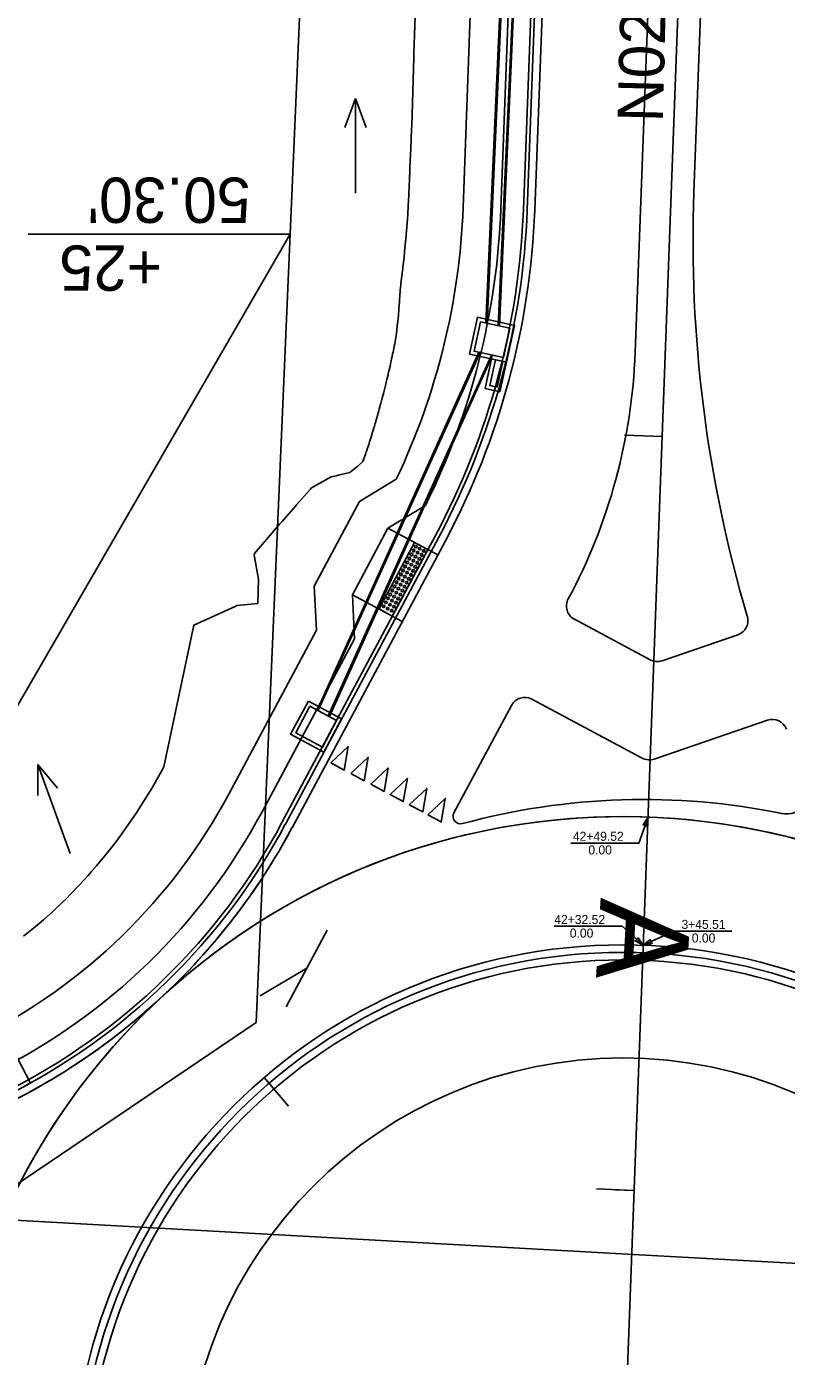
# Model space of a CAD drawing. Extents: x 670017 to 673226, y 705371 to 707498.
# Drawn here: x 671647.7 to 671748.4, y 706559.8 to 706736.1 of the extents above; entities that cross this region are included whole.
import ezdxf

# ---------------------------------------------------------------- set-up
doc = ezdxf.new("R2010")
doc.units = 0
for name, color, linetype in [('EL L 264', 7, 'Continuous'), ('EL L SCBV', 7, 'Continuous'), ('R_Drainage Flow Lines', 7, 'Continuous'), ('R_Drainage Stage 1A', 7, 'Continuous'), ('R_Horz Alg', 7, 'Continuous'), ('R_Horz Alg Station', 7, 'Continuous'), ('R_Horz Bearing', 7, 'Continuous'), ('R_No Plot', 7, 'Continuous'), ('R_No Plot FOC', 7, 'Continuous'), ('R_Proposed Const Limits Stage 1A', 7, 'Continuous'), ('R_Proposed Median', 7, 'Continuous'), ('R_Proposed RAB', 7, 'Continuous'), ('R_Proposed Road Stage 1A', 7, 'Continuous'), ('R_Proposed Sidewalk Stage 1A', 7, 'Continuous'), ('R_ROW', 7, 'Continuous'), ('R_ROW Annot', 7, 'Continuous'), ('R_Striping', 7, 'Continuous'), ('R_Water Annot', 7, 'Continuous'), ('S_EXIST_ROW', 7, 'Continuous')]:
    doc.layers.add(name, color=color, linetype=linetype)

# ---------------------------------------------------------------- blocks, each defined once
blk = doc.blocks.new('FLOW ARROW')
at = {"layer": 'R_Water Annot'}
for p, q in [((-12.57, 0), (0, 0)), ((0, 0), (-3.85, 1.4)), ((0, 0), (-3.85, -1.4))]:
    blk.add_line(p, q, dxfattribs=at)

msp = doc.modelspace()

# ---------------------------------------------------------------- linework, layer by layer
at = {"layer": 'EL L 264'}
for centre, radius, start, end in [((671726.73, 706541.35), 90, 43.8918, 132.897), ((671726.73, 706541.35), 90, 43.8918, 132.897), ((671607.03, 706670.39), 86, 296.5471, 312.7972)]:
    msp.add_arc(centre, radius, start, end, dxfattribs=at)
at = {"layer": 'EL L SCBV'}
for p, q in [((671722.16, 706902.25), (671715.06, 706711.75)), ((671703.22, 706667.92), (671682.89, 706629.86))]:
    msp.add_line(p, q, dxfattribs=at)
for centre, radius, start, end in [((671614.13, 706715.51), 101, 331.8875, 357.8657), ((671607.03, 706670.39), 86, 312.7924, 331.8875), ((671726.73, 706541.35), 90, 132.9015, 220.6505)]:
    msp.add_arc(centre, radius, start, end, dxfattribs=at)
at = {"layer": 'R_Drainage Stage 1A'}
for p, q in [((671708.58, 706696.8), (671717.8, 706902.55)), ((671708.75, 706696.77), (671717.97, 706902.54)), ((671710.23, 706696.44), (671719.47, 706902.44)), ((671710.4, 706696.41), (671719.63, 706902.43)), ((671686.22, 706645.48), (671707.64, 706692.92)), ((671686.37, 706645.4), (671707.81, 706692.88)), ((671687.7, 706644.7), (671709.31, 706692.55)), ((671687.84, 706644.62), (671709.47, 706692.51))]:
    msp.add_line(p, q, dxfattribs=at)
for points in [[(671707.49, 706697.56), (671706.42, 706692.67), (671711.31, 706691.6), (671712.38, 706696.48)], [(671707.87, 706696.96), (671707.02, 706693.05), (671710.92, 706692.2), (671711.78, 706696.1)], [(671711.31, 706691.6), (671710.45, 706687.69), (671708.49, 706688.12), (671709.35, 706692.03)], [(671710.82, 706691.71), (671710.07, 706688.29), (671709.09, 706688.5), (671709.84, 706691.92)], [(671685.06, 706646.67), (671682.71, 706642.26), (671687.12, 706639.9), (671689.47, 706644.31)], [(671685.27, 706645.99), (671683.38, 706642.46), (671686.91, 706640.58), (671688.8, 706644.11)], [(671645.92, 706600.44), (671641.49, 706598.13), (671643.8, 706593.7), (671648.24, 706596.01)]]:
    msp.add_lwpolyline(points, close=True, dxfattribs=at)
at = {"layer": 'R_Horz Alg'}
msp.add_line((671726.73, 706541.35), (671758.33, 707389.39), dxfattribs=at)
msp.add_circle((671726.73, 706541.35), 73, dxfattribs=at)
at = {"layer": 'R_Horz Alg Station'}
for points in [[(671726.96, 706681.92), (671731.96, 706681.73)], [(671729.46, 706681.82), (671731.96, 706681.73)], [(671682.44, 706592.95), (671679.18, 706596.75)], [(671723.24, 706581.98), (671728.23, 706581.8)], [(671725.73, 706581.89), (671728.23, 706581.8)]]:
    msp.add_lwpolyline(points, dxfattribs=at)
at = {"layer": 'R_No Plot'}
for p, q in [((671727.67, 706627.84), (671719.85, 706627.84)), ((671682.13, 706606.15), (671687.55, 706616.31)), ((671725.46, 706616.81), (671717.63, 706616.81)), ((671741.19, 706616.16), (671734.72, 706616.16)), ((671678.68, 706607.57), (671684.86, 706611.28))]:
    msp.add_line(p, q, dxfattribs=at)
for points in [[(671730.08, 706631.29), (671728.87, 706627.84), (671727.67, 706627.84)], [(671729.44, 706614.3), (671726.66, 706616.81), (671725.46, 706616.81)], [(671729.44, 706614.3), (671733.52, 706616.16), (671734.72, 706616.16)]]:
    msp.add_lwpolyline(points, dxfattribs=at)
for points in [[(671730.08, 706631.29), (671729.97, 706630.09), (671729.42, 706630.28)], [(671729.44, 706614.3), (671728.38, 706614.86), (671728.77, 706615.29)], [(671729.44, 706614.3), (671730.38, 706615.05), (671730.62, 706614.52)]]:
    msp.add_lwpolyline(points, close=True, dxfattribs=at)
msp.add_circle((671726.73, 706541.35), 90, dxfattribs=at)
at = {"layer": 'R_No Plot FOC'}
for p, q in [((671714.06, 706711.79), (671721.16, 706902.28)), ((671682.01, 706630.33), (671702.34, 706668.39))]:
    msp.add_line(p, q, dxfattribs=at)
msp.add_circle((671726.73, 706541.35), 72, dxfattribs=at)
for centre, radius, start, end in [((671614.13, 706715.51), 100, 331.8875, 357.8657), ((671607.03, 706670.39), 85, 296.5471, 331.8875)]:
    msp.add_arc(centre, radius, start, end, dxfattribs=at)
at = {"layer": 'R_Proposed Const Limits Stage 1A'}
for points in [[(671692.27, 706678.43), (671692.45, 706678.91), (671692.61, 706679.39), (671692.74, 706679.77), (671692.75, 706679.8), (671692.85, 706680.07), (671693.1, 706680.83), (671693.12, 706680.88), (671693.17, 706681.06), (671693.41, 706681.77), (671693.48, 706681.99), (671693.58, 706682.32), (671693.7, 706682.72), (671693.71, 706682.75), (671693.82, 706683.11), (671693.92, 706683.47), (671693.95, 706683.59), (671694.14, 706684.24), (671694.26, 706684.66), (671694.32, 706684.87), (671694.4, 706685.17), (671694.46, 706685.37), (671694.64, 706686.03), (671694.67, 706686.15), (671694.76, 706686.5), (671694.78, 706686.58), (671694.86, 706686.87), (671695.01, 706687.44), (671695.06, 706687.64), (671695.27, 706688.49), (671695.29, 706688.57), (671695.33, 706688.74), (671695.34, 706688.78), (671695.47, 706689.32), (671695.62, 706689.93), (671695.65, 706690.05), (671695.7, 706690.28), (671695.73, 706690.42), (671695.88, 706691.09), (671695.95, 706691.37), (671696.08, 706692), (671696.14, 706692.25), (671696.16, 706692.36), (671696.22, 706692.62), (671696.23, 706692.7), (671696.28, 706692.94), (671696.38, 706693.42), (671696.44, 706693.73), (671696.51, 706694.05), (671696.56, 706694.32), (671696.61, 706694.59), (671696.73, 706695.42), (671696.74, 706695.49), (671696.78, 706695.79), (671696.8, 706695.98), (671696.84, 706696.32), (671696.89, 706696.81), (671696.9, 706696.9), (671696.91, 706697), (671696.94, 706697.35), (671696.99, 706697.84), (671697.04, 706698.52), (671697.05, 706698.69), (671697.12, 706699.59), (671697.15, 706699.99), (671697.17, 706700.27), (671697.23, 706701.21), (671697.3, 706701.82), (671697.33, 706702.01), (671697.54, 706703.69), (671697.54, 706703.73), (671697.58, 706704.01), (671697.59, 706704.18), (671697.74, 706705.46), (671697.81, 706706.18), (671697.81, 706706.21), (671697.91, 706707.18), (671698.01, 706708.34), (671698.02, 706708.4), (671698.04, 706708.66), (671698.06, 706708.91), (671698.06, 706708.95), (671698.18, 706710.6), (671698.19, 706710.64), (671698.22, 706711.16), (671698.3, 706712.37), (671698.3, 706712.52), (671698.32, 706712.88), (671698.36, 706713.91), (671698.49, 706716.91), (671698.51, 706717.52), (671698.62, 706719.92), (671698.74, 706722.51), (671698.76, 706722.93), (671698.85, 706725.95), (671698.89, 706727.51), (671698.93, 706728.96), (671699.03, 706731.98), (671699.04, 706732.51), (671699.12, 706735), (671699.21, 706737.51)], [(671678.35, 706659.59), (671678.45, 706662.85), (671677.88, 706666.01), (671677.91, 706666.22), (671679.18, 706667.72), (671679.27, 706667.82), (671679.73, 706668.36), (671680.74, 706669.53), (671681.25, 706670.12), (671681.48, 706670.39), (671681.57, 706670.49), (671683.34, 706672.53), (671683.44, 706672.64), (671685.25, 706674.69), (671685.33, 706674.78), (671685.47, 706674.94), (671688.07, 706676.41), (671688.78, 706676.55), (671688.84, 706676.56), (671690.55, 706676.97), (671690.69, 706677.08), (671690.79, 706677.16), (671691.28, 706677.54), (671691.56, 706677.76), (671692.27, 706678.43)], [(671678.35, 706659.59), (671675.63, 706659.35), (671675.35, 706659.22), (671672.61, 706657.96), (671669.86, 706656.72), (671665.91, 706637.95), (671665.56, 706637.3), (671665.37, 706636.96), (671664.34, 706635.17), (671663.31, 706633.48), (671662.54, 706632.28), (671662.27, 706631.87), (671661.23, 706630.34), (671660.18, 706628.88), (671659.48, 706627.94), (671659.12, 706627.48), (671658.27, 706626.39), (671658.05, 706626.12), (671656.97, 706624.81), (671656.32, 706624.06), (671655.86, 706623.53), (671654.74, 706622.3), (671653.56, 706621.12), (671652.99, 706620.5), (671652.4, 706619.92), (671651.18, 706618.78), (671649.93, 706617.66), (671649.38, 706617.19), (671648.63, 706616.57), (671647.29, 706615.49)]]:
    msp.add_lwpolyline(points, dxfattribs=at)
at = {"layer": 'R_Proposed Median'}
for p, q in [((671736.17, 706714.12), (671743.14, 706901.24)), ((671728.37, 706692.88), (671735.41, 706881.66)), ((671720.33, 706657.51), (671730.35, 706652.15)), ((671731.94, 706652.02), (671741.98, 706655.46)), ((671714.68, 706646.92), (671729.3, 706639.11)), ((671704.36, 706631.86), (671711.97, 706646.1)), ((671730.89, 706638.98), (671745.91, 706644.12))]:
    msp.add_line(p, q, dxfattribs=at)
for centre, radius, start, end in [((671911.04, 706707.6), 175, 177.8657, 196.493), ((671653.42, 706695.67), 75, 331.7838, 357.8657), ((671721.27, 706659.27), 2, 151.7838, 241.8875), ((671741.33, 706657.35), 2, 288.9101, 16.493), ((671731.3, 706653.91), 2, 241.8875, 288.9101), ((671713.73, 706645.16), 2, 61.8875, 151.8875), ((671746.56, 706642.23), 2, 21.3677, 108.9101), ((671730.25, 706640.87), 2, 241.8875, 288.9101), ((671748.43, 706634.7), 3, 258.4277, 21.3677), ((671729.47, 706542.12), 91.5, 78.4277, 105.1836), ((671705.24, 706631.39), 1, 151.8875, 285.1836)]:
    msp.add_arc(centre, radius, start, end, dxfattribs=at)
at = {"layer": 'R_Proposed RAB'}
for radius in [71, 58]:
    msp.add_circle((671726.73, 706541.35), radius, dxfattribs=at)
at = {"layer": 'R_Proposed Road Stage 1A'}
for p, q in [((671713.56, 706711.8), (671720.66, 706902.3)), ((671715.06, 706711.75), (671722.16, 706902.25)), ((671681.56, 706630.57), (671701.89, 706668.63)), ((671682.89, 706629.86), (671703.22, 706667.92))]:
    msp.add_line(p, q, dxfattribs=at)
for centre, radius, start, end in [((671614.13, 706715.51), 99.5, 331.8875, 357.8657), ((671614.13, 706715.51), 101, 331.8875, 357.8657), ((671607.03, 706670.39), 84.5, 296.5471, 331.8875), ((671607.03, 706670.39), 86, 296.5471, 331.8875)]:
    msp.add_arc(centre, radius, start, end, dxfattribs=at)
at = {"layer": 'R_Proposed Sidewalk Stage 1A'}
for p, q in [((671705.57, 706712.1), (671712.67, 706902.74)), ((671710.57, 706711.92), (671717.67, 706902.48)), ((671691.84, 706673.14), (671696.71, 706676.11)), ((671691.84, 706673.14), (671685.83, 706661.9)), ((671695.6, 706669.58), (671700.57, 706672.6)), ((671695.6, 706669.58), (671690.89, 706660.76)), ((671702.22, 706666.05), (671695.6, 706669.58)), ((671699.13, 706667.7), (671694.42, 706658.88)), ((671685.83, 706661.9), (671686.12, 706656.07)), ((671697.51, 706657.23), (671690.89, 706660.76)), ((671690.89, 706660.76), (671691.18, 706654.94)), ((671674.51, 706634.34), (671686.12, 706656.07)), ((671678.92, 706631.98), (671691.18, 706654.94))]:
    msp.add_line(p, q, dxfattribs=at)
msp.add_lwpolyline([(671700.89, 706666.75), (671696.18, 706657.93), (671694.42, 706658.88), (671699.13, 706667.7)], close=True, dxfattribs=at)
for centre in [(671699.01, 706666.63), (671699.3, 706667.15), (671699.54, 706666.34), (671699.82, 706666.87), (671700.35, 706666.59), (671697.88, 706664.51), (671698.16, 706665.04), (671698.45, 706665.57), (671698.69, 706664.76), (671698.73, 706666.1), (671698.98, 706665.28), (671699.22, 706664.47), (671699.26, 706665.81), (671699.51, 706665), (671699.79, 706665.53), (671700.07, 706666.06), (671697.03, 706662.92), (671697.32, 706663.45), (671697.56, 706662.64), (671697.6, 706663.98), (671697.85, 706663.17), (671698.13, 706663.7), (671698.37, 706662.88), (671698.41, 706664.23), (671698.66, 706663.41), (671698.94, 706663.94), (671696.19, 706661.33), (671696.47, 706661.86), (671696.71, 706661.05), (671696.75, 706662.39), (671697, 706661.58), (671697.28, 706662.11), (671697.53, 706661.3), (671697.81, 706661.83), (671698.09, 706662.36), (671695.05, 706659.22), (671695.34, 706659.75), (671695.62, 706660.28), (671695.87, 706659.46), (671695.9, 706660.8), (671696.15, 706659.99), (671696.4, 706659.18), (671696.43, 706660.52), (671696.68, 706659.71), (671696.96, 706660.24), (671697.24, 706660.77), (671695.58, 706658.93), (671696.11, 706658.65)]:
    msp.add_circle(centre, 0.165, dxfattribs=at)
for centre, radius, start, end in [((671614.13, 706715.51), 91.5, 334.4926, 357.8657), ((671614.13, 706715.51), 96.5, 333.5967, 357.8657), ((671607.03, 706670.39), 76.5, 296.5471, 331.8875), ((671607.03, 706670.39), 81.5, 296.5471, 331.8875)]:
    msp.add_arc(centre, radius, start, end, dxfattribs=at)
at = {"layer": 'R_ROW'}
msp.add_lwpolyline([(670753.27, 706632.89), (670820.8, 706679.41), (670885.98, 706681), (670933.29, 706628.45), (671562.42, 706595.43), (671640.16, 706635.12), (671682.63, 706708.58)], dxfattribs=at)
at = {"layer": 'R_ROW Annot'}
msp.add_lwpolyline([(671682.63, 706708.58), (671667.92, 706708.57), (671647.92, 706708.57)], dxfattribs=at)
at = {"layer": 'R_Striping'}
for points in [[(671688.04, 706638.46), (671689.81, 706637.52), (671690.34, 706640.64), (671688.04, 706638.46)], [(671690.34, 706640.64), (671688.04, 706638.46)], [(671689.81, 706637.52), (671690.34, 706640.64)], [(671692.99, 706639.23), (671690.69, 706637.05)], [(671690.69, 706637.05), (671692.45, 706636.11), (671692.99, 706639.23), (671690.69, 706637.05)], [(671692.45, 706636.11), (671692.99, 706639.23)], [(671693.34, 706635.64), (671695.1, 706634.69), (671695.63, 706637.81), (671693.34, 706635.64)], [(671695.63, 706637.81), (671693.34, 706635.64)], [(671695.1, 706634.69), (671695.63, 706637.81)], [(671698.18, 706636.46), (671695.88, 706634.28), (671697.64, 706633.34), (671698.18, 706636.46)], [(671698.18, 706636.46), (671695.88, 706634.28)], [(671697.64, 706633.34), (671698.18, 706636.46)], [(671700.74, 706635.09), (671698.44, 706632.91)], [(671698.44, 706632.91), (671700.21, 706631.97), (671700.74, 706635.09), (671698.44, 706632.91)], [(671700.21, 706631.97), (671700.74, 706635.09)], [(671703.2, 706633.77), (671700.91, 706631.6)], [(671700.91, 706631.6), (671702.67, 706630.65), (671703.2, 706633.77), (671700.91, 706631.6)], [(671702.67, 706630.65), (671703.2, 706633.77)]]:
    msp.add_lwpolyline(points, dxfattribs=at)
at = {"layer": 'S_EXIST_ROW'}
for points in [[(671682.63, 706708.58), (671684.53, 706752.74), (671688.75, 706863.46)], [(671639.86, 706578.18), (671678.12, 706604.07), (671682.63, 706708.58)], [(670020.59, 706668.53), (670619.99, 706639.58), (670619.86, 706634.58), (671728.16, 706573.3), (673225.88, 706490.48)]]:
    msp.add_lwpolyline(points, dxfattribs=at)

# ---------------------------------------------------------------- block references
at = {"layer": 'R_Drainage Flow Lines'}
for p, rotation in [((671691.3, 706726.56), 89.99999999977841), ((671649.18, 706638.25), 110.03718328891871)]:
    msp.add_blockref('FLOW ARROW', p, dxfattribs=dict(at, rotation=rotation))

# ---------------------------------------------------------------- texts
at = {"layer": 'R_Horz Alg'}
msp.add_text('A', height=12, rotation=266.6859, dxfattribs=at).set_placement((671723.8, 706620.64))
at = {"layer": 'R_Horz Bearing'}
msp.add_text('N02%%d08\'03"E', height=6, rotation=88.5162, dxfattribs=at).set_placement((671732.03, 706723.36))
at = {"layer": 'R_No Plot'}
for s, p in [('42+49.52', (671720.12, 706628.14)), ('0.00', (671722.17, 706626.34)), ('42+32.52', (671717.65, 706617.11)), ('3+45.51', (671734.51, 706616.46)), ('0.00', (671719.71, 706615.31)), ('0.00', (671735.88, 706614.66))]:
    msp.add_text(s, height=1.2, rotation=360, dxfattribs=at).set_placement(p)
at = {"layer": 'R_ROW Annot'}
for s, p in [("50.30'", (671677.39, 706716.07)), ('+25', (671665.67, 706707.07))]:
    msp.add_text(s, height=6, rotation=180, dxfattribs=at).set_placement(p)

doc.saveas('drawing.dxf')
